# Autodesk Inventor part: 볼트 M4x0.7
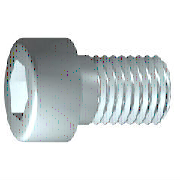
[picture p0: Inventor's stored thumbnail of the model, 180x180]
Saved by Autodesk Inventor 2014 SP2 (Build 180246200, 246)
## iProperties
IsCustomPart: 0
Created: 2015-12
Part Number: 볼트 M4x0.7
Material: 강철, 연강
Description: 6각머리 태핑 나사
Document SubType Name: Modeling
Standard: KS B 1003
Designer: mdu
Standards Organization: KS
Language: ko-KR
Size Designation: M 4 x 12
Categories: <MemberInstance><Categories><Category DisplayName="조임쇠" InternalName="e4da775c-781d-43d5-af7c-5136215cf5a6" Mnemonic="FSTN"><Category DisplayName="볼트" InternalN
Density: 7.86 g/cm^3
Mass: 2.23465 g
Surface Area: 3.30853 cm^2
Volume: 0.284306 cm^3
Appearance: 진녹색
Author: mdu
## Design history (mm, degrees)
sketch "스케치1"
  geometry: L1 (-1, 0)-(12, 0); L2 (12, 0)-(12, 2); L3 (12, 2)-(1.75, 2); L4 (1.75, 2)-(1.32, 2); L5 (1.32, 2)-(0, 2); L6 (0, 2)-(0, 3.5); L7 (0, 3.5)-(-4, 3.5); L8 (-4, 3.5)-(-4, 1.732); L9 (-4, 1.732)-(-2, 1.732); L10 (-2, 1.732)-(-1, 0); L11 (-7.2, 0)-(15.2, 0) reference; L12 (0, -0.7)-(0, 4.2) reference; L13 (1.75, 2)-(0, 2)
  constraints: 22 end point, 6 parallel, 2 collinear, 2 perpendicular, 1 horizontal, 1 point on line
  dimensions: "d1" = 10.25 distance from line of L3.end L2 (= GEL); "d2" = 0.42952 distance of L4.end L3.end (computed from GAL); "d3" = 4 distance between parallel lines of L8 L6 (= KOH); "d4" = 2 distance of L8.end L9.end (= INTI); "d5" = 60 deg angle of L10 L1; "d6" = 4 diameter of L3 L1 (= GD); "d7" = 4 diameter of L5 L1 (= BDM); "d8" = 3.4641 diameter of L9 L1 (= 1.1547 x SW); "d9" = 7 diameter of L7 L1 (= KOD); "d26" = 12 distance between parallel lines of L12 L2 (= NLG)
revolve "본체" sketch "스케치1" stored, may be unused: angle "d10" = 90 deg
sketch "스케치2"
  geometry: L1 (0, -4.9)-(0, 4.9) reference; L2 (-4.9, 0)-(4.9, 0) reference; L3 (1.732, 0)-(0.866, -1.5); L4 (0.866, -1.5)-(-0.866, -1.5); L5 (-0.866, -1.5)-(-1.732, 0); L6 (-1.732, 0)-(-0.866, 1.5); L7 (-0.866, 1.5)-(0.866, 1.5); L8 (0.866, 1.5)-(1.732, 0); 2 further points
  constraints: 12 end point, 1 coincident, 1 horizontal alignment, 1 point on line, 12 other
extrude "슬롯" join sketch "스케치2" stored distance "d11" = 10; taper "d12" = 0 deg
workplane "Work Plane1"
fillet "Fillet2" dims "d30" = 0.1 (= R)
body "Solid1"
fillet "모깎기1" dims "d17" = 0.4 (= RR)
feature "스레드" dims "d13" = 10.25 (= GEL), "d14" = 0
chamfer "모따기1" distance "d15" = 0.42941 (= -0.5 x SPD + 0.5 x GD); stored, may be unused: second distance "d16" = 0.42941 (= GUL), angle "d27" = 45 deg
other parameters: "GD" = 4 (= NND) [user parameter; used in 2 equation terms], "NLG" = 12 [user parameter; used in 1 equation term], "GEL" = 10.25 [user parameter; used in 2 equation terms], "KOD" = 7 [user parameter; used in 1 equation term], "KOH" = 4 [user parameter; used in 1 equation term], "INTI" = 2 [user parameter; used in 1 equation term], "GAL" = 0.42941 (= 0.61345 x PTC) [user parameter; used in 1 equation term], "GUL" = 0.42941 (= 0.61345 x PTC) [user parameter; used in 1 equation term], "BDM" = 4 (= NND) [user parameter; used in 1 equation term], "SW" = 3 [user parameter; used in 2 equation terms], "RR" = 0.4 [user parameter; used in 1 equation term], "SPD" = 3.14117 (= NND - 1.2269 x PTC) [user parameter; used in 1 equation term], "d19" = 0, "d28" = 0, "d29" = 0, "R" = 0.1 [user parameter; used in 1 equation term], "PHH" = 0.2 [user parameter], "GD1" = 3.14117 (= THREADDIA - 1.2269 x PTC) [user parameter], "THREADDIA" = 4 [user parameter; used in 1 equation term], "FAWI" = 45 deg [user parameter], "TPU" = 14.28571 (computed from PTC) [user parameter], "PTC" = 0.7 [user parameter; used in 5 equation terms], "NND" = 4 [user parameter; used in 3 equation terms], "TOA" = 30 deg [user parameter], "E0" = 3.465 (= 1.155 x SW) [user parameter]
